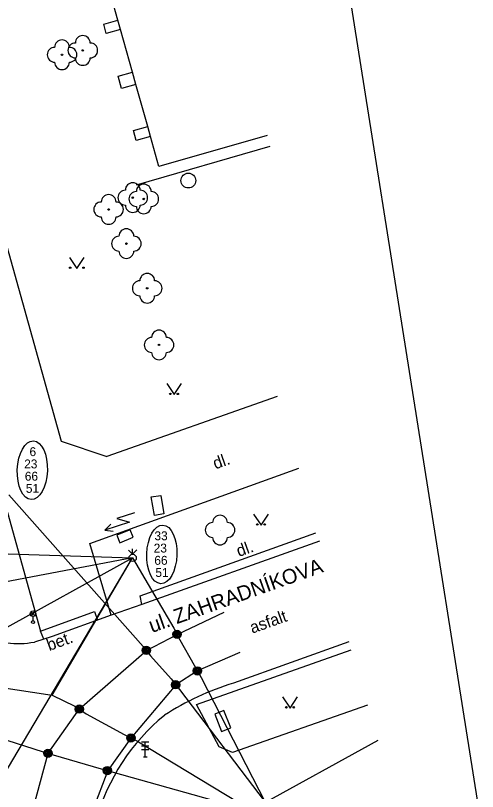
# Model space of a CAD drawing. Extents: x -599098 to -598820, y -1159597 to -1158744.
# Drawn here: x -598883.8 to -598852.7, y -1159366.1 to -1159313.7 of the extents above; entities that cross this region are included whole.
import ezdxf

# ---------------------------------------------------------------- set-up
doc = ezdxf.new("R2010")
doc.units = 0
for name, color, linetype in [('budovy', 7, 'Continuous'), ('druh pozemku stromy', 7, 'Continuous'), ('kresba', 7, 'Continuous'), ('mapový rám legenda', 7, 'Continuous'), ('popisy', 7, 'Continuous'), ('trol_detaily', 7, 'Continuous'), ('trol_převěsy', 7, 'Continuous'), ('trol_troljová stopa', 7, 'Continuous'), ('trol_ved sloupy konzoly', 7, 'Continuous'), ('trol_čísla sloupů', 7, 'Continuous'), ('značky IS', 7, 'Continuous')]:
    doc.layers.add(name, color=color, linetype=linetype)

msp = doc.modelspace()

# ---------------------------------------------------------------- linework, layer by layer
at = {"layer": 'budovy'}
for p, q in [((-598876.89, -1159314.06), (-598877.79, -1159310.83)), ((-598877.85, -1159314.33), (-598876.89, -1159314.06)), ((-598876.71, -1159314.68), (-598876.89, -1159314.06)), ((-598877.68, -1159314.95), (-598877.85, -1159314.33)), ((-598876.71, -1159314.68), (-598877.68, -1159314.95)), ((-598875.91, -1159317.57), (-598876.71, -1159314.68)), ((-598876.87, -1159317.84), (-598875.91, -1159317.57)), ((-598876.64, -1159318.66), (-598876.87, -1159317.84)), ((-598875.68, -1159318.39), (-598875.91, -1159317.57)), ((-598875.68, -1159318.39), (-598876.64, -1159318.66)), ((-598874.88, -1159321.23), (-598875.68, -1159318.39)), ((-598875.85, -1159321.5), (-598874.88, -1159321.23)), ((-598875.66, -1159322.16), (-598875.85, -1159321.5)), ((-598874.7, -1159321.89), (-598874.88, -1159321.23)), ((-598874.7, -1159321.89), (-598875.66, -1159322.16)), ((-598874.13, -1159323.92), (-598874.7, -1159321.89)), ((-598866.83, -1159321.83), (-598874.13, -1159323.92)), ((-598859.376, -1159362.613), (-598867.52, -1159367.12))]:
    msp.add_line(p, q, dxfattribs=at)
at = {"layer": 'druh pozemku stromy'}
for points in [[(-598880.16, -1159330.05), (-598879.66, -1159330.8), (-598879.16, -1159330.05)], [(-598873.605, -1159338.553), (-598873.105, -1159339.303), (-598872.605, -1159338.553)], [(-598873.605, -1159338.553), (-598873.105, -1159339.303), (-598872.605, -1159338.553)], [(-598867.748, -1159347.35), (-598867.248, -1159348.1), (-598866.748, -1159347.35)], [(-598867.748, -1159347.35), (-598867.248, -1159348.1), (-598866.748, -1159347.35)], [(-598865.79, -1159359.68), (-598865.29, -1159360.43), (-598864.79, -1159359.68)]]:
    msp.add_lwpolyline(points, dxfattribs=at)
for centre, radius in [((-598879.26, -1159316.1), 0.05), ((-598880.66, -1159316.39), 0.05), ((-598875.89, -1159326.02), 0.05), ((-598875.15, -1159326.11), 0.05), ((-598877.52, -1159326.82), 0.05), ((-598876.32, -1159329.12), 0.05), ((-598880.111, -1159330.75), 0.05), ((-598879.211, -1159330.75), 0.05), ((-598874.92, -1159332.13), 0.05), ((-598874.12, -1159335.95), 0.05), ((-598873.355, -1159339.253), 0.05), ((-598873.355, -1159339.253), 0.05), ((-598872.855, -1159339.253), 0.05), ((-598872.855, -1159339.253), 0.05), ((-598867.498, -1159348.05), 0.05), ((-598867.498, -1159348.05), 0.05), ((-598866.998, -1159348.05), 0.05), ((-598866.998, -1159348.05), 0.05), ((-598870.01, -1159348.43), 0.0005), ((-598870.01, -1159348.43), 0.0005), ((-598865.54, -1159360.38), 0.05), ((-598865.04, -1159360.38), 0.05)]:
    msp.add_circle(centre, radius, dxfattribs=at)
for centre, start, end in [((-598879.26, -1159315.6), 0, 180), ((-598880.66, -1159315.89), 0, 180), ((-598879.76, -1159316.1), 90, 270), ((-598878.76, -1159316.1), 270, 90), ((-598881.16, -1159316.39), 90, 270), ((-598880.16, -1159316.39), 270, 90), ((-598879.26, -1159316.6), 180, 0), ((-598880.66, -1159316.89), 180, 0), ((-598875.89, -1159325.52), 0, 180), ((-598875.15, -1159325.61), 0, 180), ((-598876.39, -1159326.02), 90, 270), ((-598875.65, -1159326.11), 90, 270), ((-598875.39, -1159326.02), 270, 90), ((-598874.65, -1159326.11), 270, 90), ((-598877.52, -1159326.32), 0, 180), ((-598878.02, -1159326.82), 90, 270), ((-598877.02, -1159326.82), 270, 90), ((-598875.89, -1159326.52), 180, 0), ((-598875.15, -1159326.61), 180, 0), ((-598877.52, -1159327.32), 180, 0), ((-598876.32, -1159328.62), 0, 180), ((-598876.82, -1159329.12), 90, 270), ((-598875.82, -1159329.12), 270, 90), ((-598876.32, -1159329.62), 180, 0), ((-598874.92, -1159331.63), 0, 180), ((-598875.42, -1159332.13), 90, 270), ((-598874.42, -1159332.13), 270, 90), ((-598874.92, -1159332.63), 180, 0), ((-598874.12, -1159335.45), 0, 180), ((-598874.62, -1159335.95), 90, 270), ((-598873.62, -1159335.95), 270, 90), ((-598874.12, -1159336.45), 180, 0), ((-598870.01, -1159347.93), 0, 180), ((-598870.01, -1159347.93), 0, 180), ((-598870.51, -1159348.43), 90, 270), ((-598870.51, -1159348.43), 90, 270), ((-598869.51, -1159348.43), 270, 90), ((-598869.51, -1159348.43), 270, 90), ((-598870.01, -1159348.93), 180, 360), ((-598870.01, -1159348.93), 180, 360)]:
    msp.add_arc(centre, 0.5, start, end, dxfattribs=at)
at = {"layer": 'kresba'}
for p, q in [((-598875.63, -1159325.15), (-598866.64, -1159322.55)), ((-598886.32, -1159340.16), (-598882.12, -1159355.25)), ((-598878.78, -1159349.33), (-598864.7, -1159344.25)), ((-598875.4, -1159352.87), (-598863.56, -1159348.62)), ((-598877.35, -1159354.17), (-598878.78, -1159349.33)), ((-598875.28, -1159353.44), (-598875.4, -1159352.87)), ((-598870.06, -1159363.05), (-598871.6, -1159360.2)), ((-598869.16, -1159363.43), (-598870.06, -1159363.05))]:
    msp.add_line(p, q, dxfattribs=at)
for points in [[(-598898.87, -1159277.38), (-598880.72, -1159342.43), (-598877.649, -1159343.478)], [(-598866.17, -1159339.42), (-598877.649, -1159343.478)], [(-598863.3, -1159349.17), (-598875.28, -1159353.44), (-598877.35, -1159354.17), (-598881.32, -1159355.6), (-598882.524, -1159355.98)], [(-598881.89, -1159355.78), (-598882.12, -1159355.25), (-598878.48, -1159353.92), (-598878.26, -1159354.498)], [(-598861.322, -1159355.971), (-598869.11, -1159358.75)], [(-598871.6, -1159360.2), (-598861.164, -1159356.51)], [(-598860.074, -1159360.23), (-598869.16, -1159363.43)]]:
    msp.add_lwpolyline(points, dxfattribs=at)
for centre, radius, start, end in [((-598883.578, -1159350.87), 5.217, 241.1907, 281.6482), ((-598863.703, -1159376.404), 18.464, 107.0292, 123.0046), ((-598864.968, -1159371.672), 13.888, 129.2729, 164.6281), ((-598864.968, -1159371.672), 13.888, 129.2729, 164.6281)]:
    msp.add_arc(centre, radius, start, end, dxfattribs=at)
at = {"layer": 'mapový rám legenda'}
msp.add_line((-598852.658, -1159366.632), (-598869.083, -1159262.925), dxfattribs=at)
at = {"layer": 'trol_detaily'}
for centre, radius in [((-598872.907, -1159355.456), 0.28), ((-598872.907, -1159355.456), 0.235), ((-598872.907, -1159355.456), 0.178), ((-598872.907, -1159355.456), 0.118), ((-598872.907, -1159355.456), 0.0641), ((-598874.974, -1159356.54), 0.28), ((-598874.974, -1159356.54), 0.235), ((-598874.974, -1159356.54), 0.178), ((-598874.974, -1159356.54), 0.118), ((-598874.974, -1159356.54), 0.0641), ((-598871.53, -1159357.927), 0.28), ((-598871.53, -1159357.927), 0.235), ((-598871.53, -1159357.927), 0.178), ((-598871.53, -1159357.927), 0.118), ((-598871.53, -1159357.927), 0.0641), ((-598873.003, -1159358.859), 0.28), ((-598873.003, -1159358.859), 0.235), ((-598873.003, -1159358.859), 0.178), ((-598873.003, -1159358.859), 0.118), ((-598873.003, -1159358.859), 0.0641), ((-598879.491, -1159360.502), 0.28), ((-598879.491, -1159360.502), 0.235), ((-598879.491, -1159360.502), 0.178), ((-598879.491, -1159360.502), 0.118), ((-598879.491, -1159360.502), 0.0641), ((-598876.02, -1159362.446), 0.28), ((-598876.02, -1159362.446), 0.235), ((-598876.02, -1159362.446), 0.178), ((-598876.02, -1159362.446), 0.118), ((-598876.02, -1159362.446), 0.0641), ((-598881.606, -1159363.485), 0.28), ((-598881.606, -1159363.485), 0.235), ((-598881.606, -1159363.485), 0.178), ((-598881.606, -1159363.485), 0.118), ((-598881.606, -1159363.485), 0.0641), ((-598877.603, -1159364.642), 0.28), ((-598877.603, -1159364.642), 0.235), ((-598877.603, -1159364.642), 0.178), ((-598877.603, -1159364.642), 0.118), ((-598877.603, -1159364.642), 0.0641)]:
    msp.add_circle(centre, radius, dxfattribs=at)
at = {"layer": 'trol_převěsy'}
for p, q in [((-598884.24, -1159346.05), (-598875.18, -1159356.27)), ((-598890.25, -1159349.83), (-598875.9, -1159350.31)), ((-598893.72, -1159360.11), (-598875.9, -1159350.31)), ((-598875.9, -1159350.31), (-598889.44, -1159352.87)), ((-598888.919, -1159372.178), (-598875.9, -1159350.31)), ((-598881.32, -1159359.55), (-598875.9, -1159350.31)), ((-598875.9, -1159350.31), (-598873.12, -1159355.05)), ((-598873.12, -1159355.05), (-598872.71, -1159355.83)), ((-598872.71, -1159355.83), (-598871.75, -1159357.53)), ((-598875.18, -1159356.27), (-598874.7, -1159356.9)), ((-598874.7, -1159356.9), (-598873.31, -1159358.47)), ((-598871.75, -1159357.53), (-598871.28, -1159358.38)), ((-598887.54, -1159358.62), (-598881.32, -1159359.55)), ((-598873.31, -1159358.47), (-598872.75, -1159359.18)), ((-598871.28, -1159358.38), (-598866.97, -1159366.78)), ((-598881.32, -1159359.55), (-598879.79, -1159360.3)), ((-598872.75, -1159359.18), (-598866.97, -1159366.78)), ((-598879.79, -1159360.3), (-598879.04, -1159360.81)), ((-598879.04, -1159360.81), (-598876.47, -1159362.22)), ((-598886.55, -1159361.89), (-598881.93, -1159363.39)), ((-598876.47, -1159362.22), (-598875.62, -1159362.65)), ((-598875.62, -1159362.65), (-598867.29, -1159367.67)), ((-598881.93, -1159363.39), (-598881.26, -1159363.59)), ((-598881.26, -1159363.59), (-598878.02, -1159364.52)), ((-598878.02, -1159364.52), (-598877.21, -1159364.76)), ((-598877.21, -1159364.76), (-598867.39, -1159367.49))]:
    msp.add_line(p, q, dxfattribs=at)
at = {"layer": 'trol_troljová stopa'}
for p, q in [((-598872.91, -1159355.46), (-598869.74, -1159353.96)), ((-598874.97, -1159356.54), (-598872.91, -1159355.46)), ((-598879.48, -1159360.49), (-598874.97, -1159356.54)), ((-598868.68, -1159356.69), (-598871.53, -1159357.93)), ((-598871.53, -1159357.93), (-598873, -1159358.86)), ((-598873, -1159358.86), (-598876.02, -1159362.45)), ((-598881.6, -1159363.48), (-598879.48, -1159360.49)), ((-598876.02, -1159362.45), (-598877.57, -1159364.65)), ((-598883.27, -1159369.68), (-598881.6, -1159363.48)), ((-598877.57, -1159364.65), (-598879.29, -1159369.13))]:
    msp.add_line(p, q, dxfattribs=at)
at = {"layer": 'trol_ved sloupy konzoly'}
for q in [(-598875.91, -1159349.689), (-598876.179, -1159349.794), (-598875.618, -1159349.768)]:
    msp.add_line((-598875.904, -1159350.061), q, dxfattribs=at)
msp.add_circle((-598875.9, -1159350.31), 0.248, dxfattribs=at)
at = {"layer": 'trol_čísla sloupů'}
for centre in [(-598882.663, -1159344.397), (-598873.933, -1159350.069)]:
    msp.add_ellipse(centre, major_axis=(0.073, 1.978), ratio=0.512894, dxfattribs=at)
at = {"layer": 'značky IS'}
for p, q in [((-598882.745, -1159354.205), (-598882.481, -1159353.941)), ((-598882.745, -1159354.205), (-598882.481, -1159353.941)), ((-598882.745, -1159354.205), (-598882.481, -1159353.941)), ((-598882.745, -1159354.205), (-598882.481, -1159353.941)), ((-598882.477, -1159354.203), (-598882.741, -1159353.939)), ((-598882.477, -1159354.203), (-598882.741, -1159353.939)), ((-598882.477, -1159354.203), (-598882.741, -1159353.939)), ((-598882.477, -1159354.203), (-598882.741, -1159353.939)), ((-598882.613, -1159354.536), (-598882.613, -1159354.261)), ((-598882.613, -1159354.536), (-598882.613, -1159354.261)), ((-598882.613, -1159354.536), (-598882.613, -1159354.261)), ((-598882.613, -1159354.536), (-598882.613, -1159354.261)), ((-598874.804, -1159362.727), (-598875.304, -1159362.727)), ((-598874.804, -1159362.727), (-598875.304, -1159362.727)), ((-598875.054, -1159363.727), (-598875.054, -1159362.727)), ((-598875.054, -1159363.727), (-598875.054, -1159362.727)), ((-598875.304, -1159362.977), (-598874.804, -1159362.977)), ((-598875.304, -1159362.977), (-598874.804, -1159362.977)), ((-598875.304, -1159363.227), (-598874.804, -1159363.227)), ((-598875.304, -1159363.227), (-598874.804, -1159363.227)), ((-598875.179, -1159363.727), (-598874.929, -1159363.727)), ((-598875.179, -1159363.727), (-598874.929, -1159363.727))]:
    msp.add_line(p, q, dxfattribs=at)
for points in [[(-598874.43, -1159347.45), (-598874.644, -1159346.198), (-598874.01, -1159346.09), (-598873.796, -1159347.342)], [(-598874.43, -1159347.45), (-598874.644, -1159346.198), (-598874.01, -1159346.09), (-598873.796, -1159347.342)], [(-598876.96, -1159348.77), (-598876.754, -1159349.282), (-598875.855, -1159348.92), (-598876.061, -1159348.408)], [(-598876.96, -1159348.77), (-598876.754, -1159349.282), (-598875.855, -1159348.92), (-598876.061, -1159348.408)], [(-598876.96, -1159348.77), (-598876.754, -1159349.282), (-598875.855, -1159348.92), (-598876.061, -1159348.408)], [(-598876.96, -1159348.77), (-598876.754, -1159349.282), (-598875.855, -1159348.92), (-598876.061, -1159348.408)], [(-598870.36, -1159360.84), (-598869.903, -1159362.001), (-598869.29, -1159361.76), (-598869.747, -1159360.599)], [(-598870.36, -1159360.84), (-598869.903, -1159362.001), (-598869.29, -1159361.76), (-598869.747, -1159360.599)]]:
    msp.add_lwpolyline(points, close=True, dxfattribs=at)
for points in [[(-598875.782, -1159347.266), (-598876.972, -1159347.647), (-598876.106, -1159347.895), (-598877.773, -1159348.428)], [(-598877.373, -1159348.037), (-598877.773, -1159348.428), (-598877.22, -1159348.513)]]:
    msp.add_lwpolyline(points, dxfattribs=at)
for centre, radius in [((-598872.15, -1159324.87), 0.5), ((-598882.613, -1159354.073), 0.188), ((-598882.613, -1159354.073), 0.188), ((-598882.613, -1159354.073), 0.188), ((-598882.613, -1159354.073), 0.188), ((-598882.613, -1159354.636), 0.1), ((-598882.613, -1159354.636), 0.1), ((-598882.613, -1159354.636), 0.1), ((-598882.613, -1159354.636), 0.1)]:
    msp.add_circle(centre, radius, dxfattribs=at)

# ---------------------------------------------------------------- texts
at = {"layer": 'popisy'}
for s, height, rotation, p in [('dl.', 0.8, 19.4677, (-598870.323, -1159344.344)), ('dl.', 0.8, 19.4677, (-598870.323, -1159344.344)), ('dl.', 0.8, 19.7457, (-598868.739, -1159350.249)), ('dl.', 0.8, 19.7457, (-598868.739, -1159350.249)), ('ul. ZAHRADNÍKOVA', 1, 19.5274, (-598874.605, -1159355.372)), ('asfalt', 0.8, 19.6371, (-598867.834, -1159355.417)), ('bet.', 0.8, 20.0715, (-598881.521, -1159356.589))]:
    msp.add_text(s, height=height, rotation=rotation, dxfattribs=at).set_placement(p)
at = {"layer": 'trol_čísla sloupů'}
for s, p in [('6', (-598882.851, -1159343.447)), ('23', (-598883.212, -1159344.274)), ('66', (-598883.169, -1159345.1)), ('51', (-598883.097, -1159345.918)), ('33', (-598874.431, -1159349.118)), ('23', (-598874.482, -1159349.945)), ('66', (-598874.439, -1159350.771)), ('51', (-598874.367, -1159351.589))]:
    msp.add_text(s, height=0.6, dxfattribs=at).set_placement(p)

doc.saveas('drawing.dxf')
